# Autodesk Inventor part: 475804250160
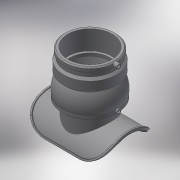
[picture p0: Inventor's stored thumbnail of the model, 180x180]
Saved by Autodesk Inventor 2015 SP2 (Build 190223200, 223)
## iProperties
Created: 2017-08
Part Number: 475804250160
Material: Generic
Description: PLASSON WASTEWATER SADDLE 225-250X160 EF ADJUSTABLE INLET
Document SubType Name: Modeling
Designer: Кирилл
Density: 1 g/cm^3
Appearance: Default
Author: Кирилл
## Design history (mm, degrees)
derived "475804.ipt"
feature "Solid1::475804.ipt"
feature "Solid2::475804.ipt"
tag "TaggingFeature1"
body "Solid1"
body "Solid2"
other parameters: "d0" = 161.6, "d3" = 45 deg, "d4" = 184, "d5" = 176, "d6" = 142.208, "d7" = 129.28, "d8" = 144, "d13" = 45 deg, "d15" = 135 deg, "d17" = 192, "d18" = 45 deg, "d19" = 80.8, "d22" = 4, "d23" = 16.16, "d25" = 45 deg, "d26" = 15 deg, "d27" = 262.6, "d28" = 136, "d29" = 156.8, "d32" = 202, "d37" = 0, "d38" = 225, "d39" = 112.5, "d40" = 267.5, "d42" = 0, "d53" = 6.75, "d55" = 0.9, "d56" = 224, "d57" = 0, "d58" = 105, "d59" = 15, "d61" = 5 deg, "d62" = 15, "d65" = 4, "d66" = 4, "d67" = 14, "d68" = 0, "d69" = 3, "d70" = 0, "B_" = 225, "H_" = 202, "A_" = 105, "d21" = 4
